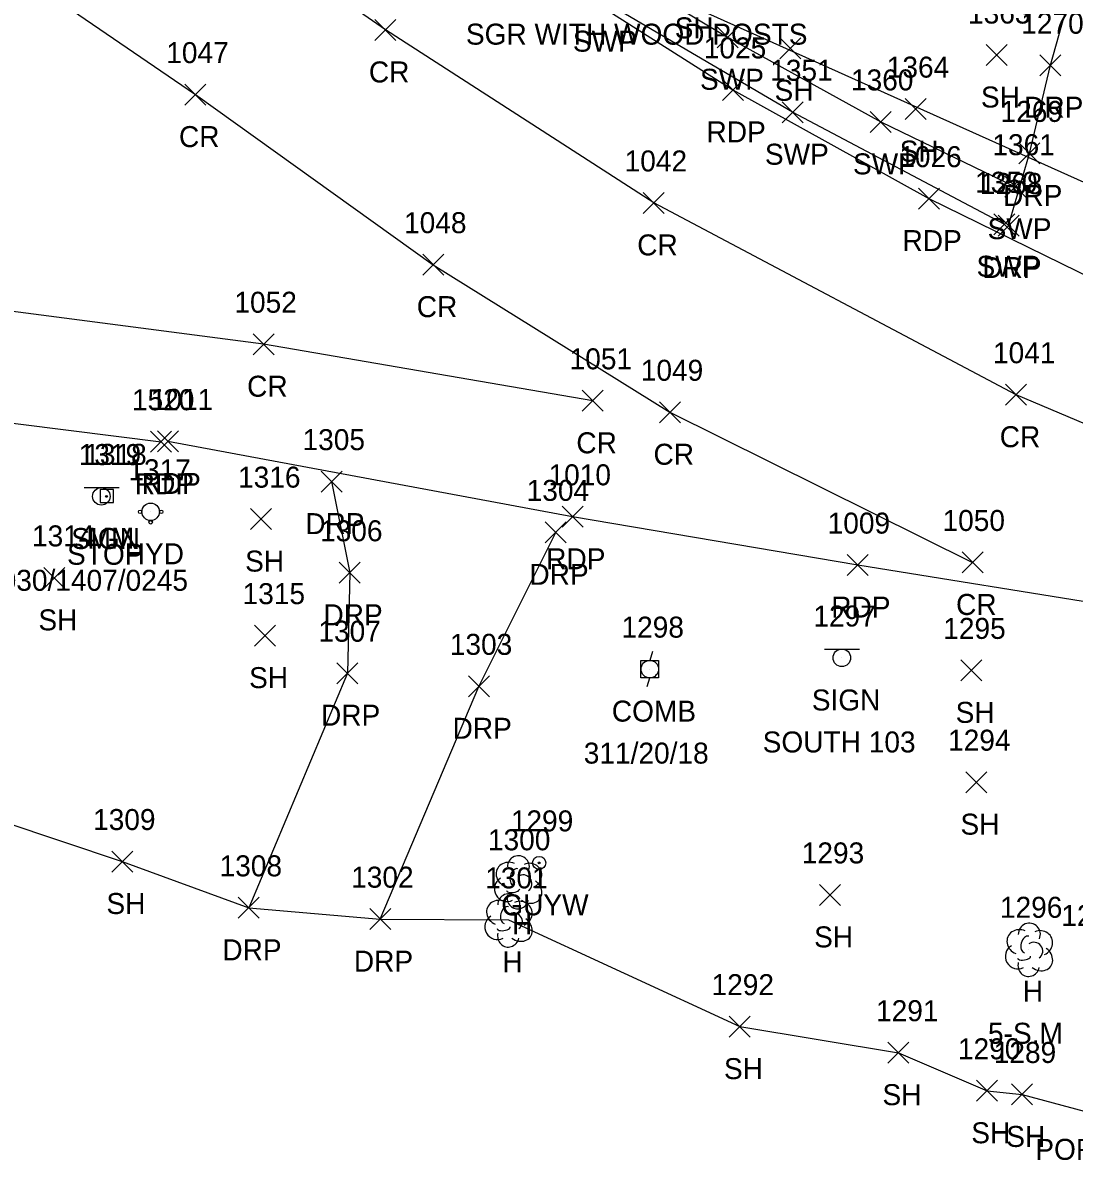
# Model space of a CAD drawing. Extents: x 1616726 to 1619875, y 273782 to 276557.
# Drawn here: x 1617044.9 to 1617145, y 276102.2 to 276211.4 of the extents above; entities that cross this region are included whole.
import ezdxf

# ---------------------------------------------------------------- set-up
doc = ezdxf.new("R2010")
doc.units = 0
for name, color, linetype in [('DCP', 7, 'Continuous'), ('L_A', 7, 'Continuous'), ('L_C', 7, 'Continuous'), ('L_I', 7, 'Continuous'), ('L_TIC', 7, 'Continuous'), ('LSOGP', 7, 'Continuous'), ('LTD', 7, 'Continuous'), ('P_A', 7, 'Continuous'), ('P_I', 7, 'Continuous'), ('P_TIC', 7, 'Continuous'), ('PET', 7, 'Continuous'), ('PRC', 7, 'Continuous'), ('R_A', 7, 'Continuous'), ('R_C', 7, 'Continuous'), ('R_I', 7, 'Continuous'), ('R_TIC', 7, 'Continuous'), ('RDP', 7, 'Continuous'), ('RSW', 7, 'Continuous'), ('S_A', 7, 'Continuous'), ('S_C', 7, 'Continuous'), ('S_I', 7, 'Continuous'), ('SRM', 7, 'Continuous'), ('SSGN', 7, 'Continuous'), ('U_A', 7, 'Continuous'), ('U_C', 7, 'Continuous'), ('U_I', 7, 'Continuous'), ('UP', 7, 'Continuous'), ('UPGW', 7, 'Continuous'), ('UWFH', 7, 'Continuous')]:
    doc.layers.add(name, color=color, linetype=linetype)

msp = doc.modelspace()

# ---------------------------------------------------------------- linework, layer by layer
at = {"layer": 'DCP'}
msp.add_lwpolyline([(1617248.53, 276150.1), (1617074.52, 276228.27)], dxfattribs=at)
at = {"layer": 'L_TIC'}
for points in [[(1617116.97, 276207.96), (1617118.97, 276209.96)], [(1617118.97, 276207.96), (1617116.97, 276209.96)], [(1617136.62, 276207.32), (1617138.62, 276209.32)], [(1617138.62, 276207.32), (1617136.62, 276209.32)], [(1617128.89, 276202.17), (1617130.89, 276204.17)], [(1617130.89, 276202.17), (1617128.89, 276204.17)], [(1617066.53, 276163.11), (1617068.53, 276165.11)], [(1617068.53, 276163.11), (1617066.53, 276165.11)], [(1617046.84, 276157.51), (1617048.84, 276159.51)], [(1617048.84, 276157.51), (1617046.84, 276159.51)], [(1617066.91, 276152.01), (1617068.91, 276154.01)], [(1617068.91, 276152.01), (1617066.91, 276154.01)], [(1617134.21, 276148.7), (1617136.21, 276150.7)], [(1617136.21, 276148.7), (1617134.21, 276150.7)], [(1617134.67, 276138.05), (1617136.67, 276140.05)], [(1617136.67, 276138.05), (1617134.67, 276140.05)], [(1617053.32, 276130.49), (1617055.32, 276132.49)], [(1617055.32, 276130.49), (1617053.32, 276132.49)], [(1617120.74, 276127.31), (1617122.74, 276129.31)], [(1617122.74, 276127.31), (1617120.74, 276129.31)], [(1617112.14, 276114.76), (1617114.14, 276116.76)], [(1617114.14, 276114.76), (1617112.14, 276116.76)], [(1617127.25, 276112.28), (1617129.25, 276114.28)], [(1617129.25, 276112.28), (1617127.25, 276114.28)], [(1617135.7, 276108.65), (1617137.7, 276110.65)], [(1617137.7, 276108.65), (1617135.7, 276110.65)], [(1617139.03, 276108.3), (1617141.03, 276110.3)], [(1617141.03, 276108.3), (1617139.03, 276110.3)]]:
    msp.add_lwpolyline(points, dxfattribs=at)
at = {"layer": 'LSOGP'}
msp.add_lwpolyline([(1616868.68, 276170.68), (1616889.93, 276166.26), (1616914.47, 276162.37), (1616938.21, 276157.87), (1616961.67, 276152.23), (1616975.36, 276145.27), (1617009.96, 276137.1), (1617027.24, 276138.17), (1617037.14, 276137.25), (1617054.32, 276131.49), (1617066.36, 276127.08), (1617078.89, 276126), (1617091.1, 276125.93), (1617113.14, 276115.76), (1617128.25, 276113.28), (1617136.7, 276109.65), (1617140.03, 276109.3), (1617154.79, 276105.34)], dxfattribs=at)
at = {"layer": 'LTD'}
for p, q in [((1617092.01, 276129.56), (1617092.01, 276129.56)), ((1617092.01, 276129.56), (1617092.01, 276129.56)), ((1617091.1, 276125.93), (1617091.1, 276125.93)), ((1617091.1, 276125.93), (1617091.1, 276125.93)), ((1617140.67, 276123.13), (1617140.67, 276123.13)), ((1617140.67, 276123.13), (1617140.67, 276123.13))]:
    msp.add_line(p, q, dxfattribs=at)
for centre in [(1617092.05, 276130.99), (1617091.14, 276127.37), (1617140.72, 276124.57)]:
    msp.add_arc(centre, 1.05, 335.5272, 180.9563, dxfattribs=at)
for centre, major_axis, ratio, start_param, end_param in [((1617091.22, 276130.22), (1.21, -0.51), 0.895232, 1.570796, 4.712389), ((1617091.8, 276130.01), (-0.208, -0.792), 0.645439, 3.141593, 6.283185), ((1617093.05, 276130.14), (-1.14, -0.48), 0.949671, 1.570796, 4.712389), ((1617090.92, 276128.85), (0.58, -1.04), 0.959034, 3.141593, 6.283185), ((1617092.51, 276129.39), (-0.5, 0.667), 0.989748, 3.141593, 6.283185), ((1617091.55, 276128.81), (-0.625, -0.083), 0.423636, 0, 3.141593), ((1617093.01, 276128.72), (-1.09, 0.79), 0.841452, 1.570796, 4.712389), ((1617090.31, 276126.6), (1.21, -0.51), 0.895232, 1.570796, 4.712389), ((1617092.01, 276128.06), (0.26, 1.06), 0.942809, 1.570796, 4.712389), ((1617092.14, 276126.52), (-1.14, -0.48), 0.949671, 1.570796, 4.712389), ((1617090.89, 276126.39), (-0.208, -0.792), 0.645439, 3.141593, 6.283185), ((1617091.6, 276125.77), (-0.5, 0.667), 0.989748, 3.141593, 6.283185), ((1617090.01, 276125.23), (0.58, -1.04), 0.959034, 3.141593, 6.283185), ((1617092.1, 276125.1), (-1.09, 0.79), 0.841452, 1.570796, 4.712389), ((1617091.1, 276124.43), (0.26, 1.06), 0.942809, 1.570796, 4.712389), ((1617090.64, 276125.18), (-0.625, -0.083), 0.423636, 0, 3.141593), ((1617139.88, 276123.8), (1.21, -0.51), 0.895232, 1.570796, 4.712389), ((1617140.46, 276123.59), (-0.208, -0.792), 0.645439, 3.141593, 6.283185), ((1617141.71, 276123.72), (-1.14, -0.48), 0.949671, 1.570796, 4.712389), ((1617139.59, 276122.43), (0.58, -1.04), 0.959034, 3.141593, 6.283185), ((1617141.17, 276122.97), (-0.5, 0.667), 0.989748, 3.141593, 6.283185), ((1617141.67, 276122.3), (-1.09, 0.79), 0.841452, 1.570796, 4.712389), ((1617140.21, 276122.38), (-0.625, -0.083), 0.423636, 0, 3.141593), ((1617140.67, 276121.63), (0.26, 1.06), 0.942809, 1.570796, 4.712389)]:
    msp.add_ellipse(centre, major_axis=major_axis, ratio=ratio, start_param=start_param, end_param=end_param, dxfattribs=at)
at = {"layer": 'P_TIC'}
for points in [[(1617078.38, 276209.71), (1617080.38, 276211.71)], [(1617080.38, 276209.71), (1617078.38, 276211.71)], [(1617060.28, 276203.55), (1617062.28, 276205.55)], [(1617062.28, 276203.55), (1617060.28, 276205.55)], [(1617111.48, 276204), (1617113.48, 276206)], [(1617113.48, 276204), (1617111.48, 276206)], [(1617103.94, 276193.23), (1617105.94, 276195.23)], [(1617105.94, 276193.23), (1617103.94, 276195.23)], [(1617130.16, 276193.64), (1617132.16, 276195.64)], [(1617132.16, 276193.64), (1617130.16, 276195.64)], [(1617082.94, 276187.35), (1617084.94, 276189.35)], [(1617084.94, 276187.35), (1617082.94, 276189.35)], [(1617066.78, 276179.77), (1617068.78, 276181.77)], [(1617068.78, 276179.77), (1617066.78, 276181.77)], [(1617138.46, 276174.96), (1617140.46, 276176.96)], [(1617140.46, 276174.96), (1617138.46, 276176.96)], [(1617098.13, 276174.38), (1617100.13, 276176.38)], [(1617100.13, 276174.38), (1617098.13, 276176.38)], [(1617105.49, 276173.29), (1617107.49, 276175.29)], [(1617107.49, 276173.29), (1617105.49, 276175.29)], [(1617057.02, 276170.48), (1617059.02, 276172.48)], [(1617059.02, 276170.48), (1617057.02, 276172.48)], [(1617057.67, 276170.51), (1617059.67, 276172.51)], [(1617059.67, 276170.51), (1617057.67, 276172.51)], [(1617096.21, 276163.33), (1617098.21, 276165.33)], [(1617098.21, 276163.33), (1617096.21, 276165.33)], [(1617123.37, 276158.73), (1617125.37, 276160.73)], [(1617125.37, 276158.73), (1617123.37, 276160.73)], [(1617134.31, 276158.98), (1617136.31, 276160.98)], [(1617136.31, 276158.98), (1617134.31, 276160.98)]]:
    msp.add_lwpolyline(points, dxfattribs=at)
at = {"layer": 'PET'}
for points in [[(1616769.24, 276246.91), (1616790.9, 276236.62), (1616808.6, 276228.19), (1616836.41, 276217.31), (1616861.69, 276208.81), (1616891.18, 276199.57), (1616916.28, 276193.27), (1616944.97, 276187.68), (1616979.27, 276181.76), (1617009.13, 276177.18), (1617040.1, 276173.73), (1617058.02, 276171.48)], [(1616989.43, 276201.18), (1617018.47, 276198.31), (1617030.26, 276200.68), (1617036.67, 276206.24), (1617039.51, 276213.46), (1617039.81, 276219.44), (1617036.61, 276227.11), (1617032.44, 276230.39), (1617046.65, 276234.32), (1617061.09, 276238.88), (1617067.9, 276234.23), (1617072.4, 276230.99), (1617088.6, 276220.19), (1617112.48, 276205), (1617131.16, 276194.64), (1617156.36, 276182.31), (1617186.3, 276169.87), (1617215.5, 276159.97), (1617247.44, 276151.44), (1617259.73, 276148.35), (1617264.1, 276152.29), (1617286.33, 276147.09), (1617304.44, 276145.41), (1617352.2, 276136.04)], [(1617343.6, 276102.19), (1617300.74, 276111.11), (1617263.27, 276119.69), (1617236.26, 276126.17), (1617212.86, 276130.65), (1617190.89, 276138.89), (1617148.81, 276155.79), (1617124.37, 276159.73), (1617097.21, 276164.33), (1617058.67, 276171.51)]]:
    msp.add_lwpolyline(points, dxfattribs=at)
at = {"layer": 'PRC'}
for points in [[(1617347.13, 276116.47), (1617295.92, 276127), (1617256.55, 276135.98), (1617216.87, 276146.76), (1617173.09, 276161.72), (1617139.46, 276175.96), (1617104.94, 276194.23), (1617079.38, 276210.71), (1617058.93, 276224.92), (1617047.07, 276234.03)], [(1617041.64, 276217.98), (1617061.28, 276204.55), (1617083.94, 276188.35), (1617106.49, 276174.29), (1617135.31, 276159.98)], [(1617099.13, 276175.38), (1617067.78, 276180.77), (1617038.54, 276184.6), (1617011.24, 276187.55), (1616987.63, 276190.62)]]:
    msp.add_lwpolyline(points, dxfattribs=at)
at = {"layer": 'R_TIC'}
for points in [[(1617110.98, 276209.01), (1617112.98, 276211.01)], [(1617112.98, 276209.01), (1617110.98, 276211.01)], [(1617141.73, 276206.35), (1617143.73, 276208.35)], [(1617143.73, 276206.35), (1617141.73, 276208.35)], [(1617117.17, 276201.87), (1617119.17, 276203.87)], [(1617119.17, 276201.87), (1617117.17, 276203.87)], [(1617125.56, 276200.95), (1617127.56, 276202.95)], [(1617127.56, 276200.95), (1617125.56, 276202.95)], [(1617139.73, 276197.95), (1617141.73, 276199.95)], [(1617141.73, 276197.95), (1617139.73, 276199.95)], [(1617138.38, 276194.78), (1617140.38, 276196.78)], [(1617140.38, 276194.78), (1617138.38, 276196.78)], [(1617137.33, 276191.2), (1617139.33, 276193.2)], [(1617139.33, 276191.2), (1617137.33, 276193.2)], [(1617137.75, 276191.08), (1617139.75, 276193.08)], [(1617139.75, 276191.08), (1617137.75, 276193.08)], [(1617073.26, 276166.68), (1617075.26, 276168.68)], [(1617075.26, 276166.68), (1617073.26, 276168.68)], [(1617094.61, 276161.85), (1617096.61, 276163.85)], [(1617096.61, 276161.85), (1617094.61, 276163.85)], [(1617074.99, 276158), (1617076.99, 276160)], [(1617076.99, 276158), (1617074.99, 276160)], [(1617074.77, 276148.43), (1617076.77, 276150.43)], [(1617076.77, 276148.43), (1617074.77, 276150.43)], [(1617087.29, 276147.18), (1617089.29, 276149.18)], [(1617089.29, 276147.18), (1617087.29, 276149.18)], [(1617065.36, 276126.08), (1617067.36, 276128.08)], [(1617067.36, 276126.08), (1617065.36, 276128.08)], [(1617077.89, 276125), (1617079.89, 276127)], [(1617079.89, 276125), (1617077.89, 276127)]]:
    msp.add_lwpolyline(points, dxfattribs=at)
at = {"layer": 'RDP'}
for points in [[(1617138.75, 276192.08), (1617140.73, 276198.95), (1617142.73, 276207.35), (1617147.72, 276225.14)], [(1617074.26, 276167.68), (1617075.99, 276159), (1617075.77, 276149.43), (1617066.36, 276127.08)], [(1617078.89, 276126), (1617088.29, 276148.18), (1617095.61, 276162.85)]]:
    msp.add_lwpolyline(points, dxfattribs=at)
at = {"layer": 'RSW'}
msp.add_lwpolyline([(1617138.33, 276192.2), (1617118.17, 276202.87), (1617099.87, 276213.64), (1617083.83, 276224.05), (1617072.72, 276231.61), (1617068.61, 276234.58), (1617070.34, 276236.96), (1617080.58, 276229.54), (1617097.68, 276218.59), (1617111.98, 276210.01), (1617126.56, 276201.95), (1617139.38, 276195.78)], dxfattribs=at)
at = {"layer": 'SRM'}
for p, q in [((1617053.47, 276166.93), (1617052.22, 276166.93)), ((1617052.22, 276166.93), (1617052.22, 276165.68)), ((1617053.47, 276166.93), (1617052.22, 276166.93)), ((1617052.22, 276166.93), (1617052.22, 276165.68)), ((1617053.47, 276165.68), (1617053.47, 276166.93)), ((1617053.47, 276165.68), (1617053.47, 276166.93)), ((1617052.22, 276165.68), (1617053.47, 276165.68)), ((1617052.22, 276165.68), (1617053.47, 276165.68))]:
    msp.add_line(p, q, dxfattribs=at)
msp.add_circle((1617052.82, 276166.27), 0.0833, dxfattribs=at)
at = {"layer": 'SSGN'}
for p, q in [((1617050.68, 276167.11), (1617054.01, 276167.11)), ((1617052.33, 276166.28), (1617052.33, 276166.28)), ((1617121.22, 276151.73), (1617124.55, 276151.73)), ((1617122.86, 276150.9), (1617122.86, 276150.9))]:
    msp.add_line(p, q, dxfattribs=at)
for centre in [(1617052.33, 276166.28), (1617122.86, 276150.9)]:
    msp.add_circle(centre, 0.833, dxfattribs=at)
at = {"layer": 'UP'}
for p, q in [((1617103.73, 276148.99), (1617103.73, 276150.65)), ((1617103.73, 276150.65), (1617105.4, 276150.65)), ((1617104.82, 276151.49), (1617104.57, 276150.65)), ((1617105.4, 276150.65), (1617105.4, 276148.99)), ((1617104.57, 276149.82), (1617104.57, 276149.82)), ((1617105.4, 276148.99), (1617103.73, 276148.99)), ((1617104.32, 276148.15), (1617104.57, 276148.99))]:
    msp.add_line(p, q, dxfattribs=at)
msp.add_circle((1617104.57, 276149.82), 0.833, dxfattribs=at)
at = {"layer": 'UPGW'}
for radius in [0.625, 0.0833]:
    msp.add_circle((1617094.03, 276131.36), radius, dxfattribs=at)
at = {"layer": 'UWFH'}
msp.add_line((1617057.03, 276164.81), (1617057.03, 276164.81), dxfattribs=at)
for centre, radius in [((1617056.03, 276164.81), 0.167), ((1617057.03, 276164.81), 0.833), ((1617058.03, 276164.81), 0.167), ((1617057.03, 276163.81), 0.167)]:
    msp.add_circle(centre, radius, dxfattribs=at)

# ---------------------------------------------------------------- texts
at = {"layer": 'L_A'}
for s, p in [('SH', (1617106.94, 276209.91)), ('SH', (1617116.45, 276203.96)), ('SH', (1617136.11, 276203.32)), ('SH', (1617128.37, 276198.17)), ('SH', (1617066.02, 276159.11)), ('SH', (1617046.33, 276153.51)), ('SH', (1617066.4, 276148.01)), ('SH', (1617133.7, 276144.7)), ('SH', (1617134.16, 276134.05)), ('SH', (1617052.81, 276126.49)), ('H', (1617091.44, 276124.56)), ('SH', (1617120.22, 276123.31)), ('H', (1617090.53, 276120.93)), ('H', (1617140.1, 276118.13)), ('SH', (1617111.63, 276110.76)), ('SH', (1617126.73, 276108.28)), ('SH', (1617135.19, 276104.65)), ('SH', (1617138.52, 276104.3))]:
    msp.add_text(s, height=2, dxfattribs=at).set_placement(p)
at = {"layer": 'L_C'}
for s, p in [('5-S.M', (1617136.78, 276114.13)), ('PORCH BEGINS HERE', (1617141.29, 276103.07))]:
    msp.add_text(s, height=2, dxfattribs=at).set_placement(p)
at = {"layer": 'L_I'}
for s, p in [('1363', (1617134.88, 276211.32)), ('1364', (1617127.14, 276206.17)), ('1316', (1617065.35, 276167.11)), ('1314', (1617045.72, 276161.51)), ('1315', (1617065.78, 276156.01)), ('1295', (1617132.52, 276152.7)), ('1294', (1617132.98, 276142.05)), ('1309', (1617051.54, 276134.49)), ('1300', (1617089.15, 276132.56)), ('1293', (1617119.04, 276131.31)), ('1301', (1617088.89, 276128.93)), ('1296', (1617137.92, 276126.13)), ('1288', (1617143.77, 276125.35)), ('1292', (1617110.45, 276118.76)), ('1291', (1617126.12, 276116.28)), ('1290', (1617133.92, 276112.65)), ('1289', (1617137.33, 276112.3))]:
    msp.add_text(s, height=2, dxfattribs=at).set_placement(p)
at = {"layer": 'P_A'}
for s, p in [('CR', (1617077.81, 276205.71)), ('RDP', (1617109.97, 276200)), ('CR', (1617059.72, 276199.55)), ('CR', (1617103.37, 276189.23)), ('RDP', (1617128.64, 276189.64)), ('CR', (1617082.37, 276183.35)), ('CR', (1617066.21, 276175.77)), ('CR', (1617097.57, 276170.38)), ('CR', (1617137.9, 276170.96)), ('CR', (1617104.92, 276169.29)), ('RDP', (1617055.51, 276166.48)), ('RDP', (1617056.16, 276166.51)), ('RDP', (1617094.7, 276159.33)), ('CR', (1617133.74, 276154.98)), ('RDP', (1617121.85, 276154.73))]:
    msp.add_text(s, height=2, dxfattribs=at).set_placement(p)
at = {"layer": 'P_I'}
for s, p in [('1047', (1617058.51, 276207.55)), ('1025', (1617109.71, 276208)), ('1026', (1617128.33, 276197.64)), ('1042', (1617102.17, 276197.23)), ('1048', (1617081.16, 276191.35)), ('1052', (1617065, 276183.77)), ('1051', (1617096.93, 276178.38)), ('1041', (1617137.26, 276178.96)), ('1049', (1617103.71, 276177.29)), ('1520', (1617055.24, 276174.48)), ('1011', (1617057.03, 276174.51)), ('1010', (1617094.92, 276167.33)), ('1009', (1617121.51, 276162.73)), ('1050', (1617132.45, 276162.98))]:
    msp.add_text(s, height=2, dxfattribs=at).set_placement(p)
at = {"layer": 'R_A'}
for s, p in [('SWP', (1617097.24, 276208.64)), ('SWP', (1617109.35, 276205.01)), ('DRP', (1617140.22, 276202.35)), ('SWP', (1617115.53, 276197.87)), ('SWP', (1617123.92, 276196.95)), ('DRP', (1617138.22, 276193.95)), ('SWP', (1617136.74, 276190.78)), ('SWP', (1617135.69, 276187.2)), ('DRP', (1617136.24, 276187.08)), ('DRP', (1617071.75, 276162.68)), ('DRP', (1617093.1, 276157.85)), ('DRP', (1617073.48, 276154)), ('DRP', (1617073.25, 276144.43)), ('DRP', (1617085.78, 276143.18)), ('DRP', (1617063.85, 276122.08)), ('DRP', (1617076.38, 276121))]:
    msp.add_text(s, height=2, dxfattribs=at).set_placement(p)
at = {"layer": 'R_C'}
msp.add_text('SGR WITH WOOD POSTS', height=2, dxfattribs=at).set_placement((1617087.05, 276209.31))
at = {"layer": 'R_I'}
for s, p in [('1270', (1617139.95, 276210.35)), ('1351', (1617116.04, 276205.87)), ('1360', (1617123.73, 276204.95)), ('1269', (1617137.98, 276201.95)), ('1361', (1617137.2, 276198.78)), ('1350', (1617135.55, 276195.2)), ('1268', (1617136.01, 276195.08)), ('1305', (1617071.49, 276170.68)), ('1304', (1617092.84, 276165.85)), ('1306', (1617073.16, 276162)), ('1307', (1617073, 276152.43)), ('1303', (1617085.52, 276151.18)), ('1308', (1617063.59, 276130.08)), ('1302', (1617076.12, 276129))]:
    msp.add_text(s, height=2, dxfattribs=at).set_placement(p)
at = {"layer": 'S_A'}
for s, p in [('SIGN', (1617049.46, 276161.26)), ('MM', (1617051.01, 276161.28)), ('SIGN', (1617120, 276145.88))]:
    msp.add_text(s, height=2, dxfattribs=at).set_placement(p)
at = {"layer": 'S_C'}
for s, p in [('STOP', (1617049.06, 276159.76)), ('1030/1407/0245', (1617041.25, 276157.28)), ('SOUTH 103', (1617115.32, 276141.88))]:
    msp.add_text(s, height=2, dxfattribs=at).set_placement(p)
at = {"layer": 'S_I'}
for s, p in [('1319', (1617050.17, 276169.26)), ('1318', (1617050.7, 276169.28)), ('1297', (1617120.15, 276153.88))]:
    msp.add_text(s, height=2, dxfattribs=at).set_placement(p)
at = {"layer": 'U_A'}
for s, p in [('HYD', (1617054.55, 276159.81)), ('COMB', (1617100.95, 276144.82)), ('GUYW', (1617090.42, 276126.36))]:
    msp.add_text(s, height=2, dxfattribs=at).set_placement(p)
at = {"layer": 'U_C'}
msp.add_text('311/20/18', height=2, dxfattribs=at).set_placement((1617098.28, 276140.82))
at = {"layer": 'U_I'}
for s, p in [('1317', (1617054.9, 276167.81)), ('1298', (1617101.87, 276152.82)), ('1299', (1617091.33, 276134.36))]:
    msp.add_text(s, height=2, dxfattribs=at).set_placement(p)

doc.saveas('drawing.dxf')
